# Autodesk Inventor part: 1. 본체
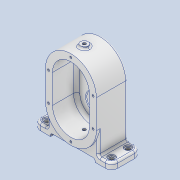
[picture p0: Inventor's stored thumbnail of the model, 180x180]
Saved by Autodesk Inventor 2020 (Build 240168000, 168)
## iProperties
Created: 2021-05
Part Number: 1. 본체
Material: 알루미늄 6061
Document SubType Name: Modeling
Designer: Owner
Density: 2.7 g/cm^3
Appearance: 알루미늄 - 평지
Author: Owner
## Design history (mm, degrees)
sketch "스케치4"
  geometry: L1 (0, -22.5)-(0, 22.5); L2 (40, -22.5)-(40, 22.5); L3 (-40, 22.5)-(-40, -22.5); A1 r 40 centre (0, -22.5) between (-40, -22.5) and (40, -22.5); A2 r 40 centre (0, 22.5) between (40, 22.5) and (-40, 22.5); 2 further points
  constraints: 8 end point, 4 point on circle, 4 tangent, 2 centre point, 1 coincident, 1 midpoint, 1 parallel, 1 vertical
  dimensions: "d15" = 40 radius of A2; "d16" = 45 distance of L3.start L3.end
extrude "돌출4" new body sketch "스케치4" stored distance "d17" = 49; taper "d18" = 0 deg
feature "쉘1" dims "d19" = 11
node "작업 평면1"
sketch "스케치5"
  geometry: L1 (-61, 24.5)-(61, 24.5); L2 (61, 24.5)-(61, -21.5); L3 (61, -21.5)-(-61, -21.5); L4 (-61, -21.5)-(-61, 24.5); L5 (0, 60.783)-(0, -54.984); L6 (90.887, 0)-(-105.505, 0); 1 further point
  constraints: 12 end point, 2 horizontal, 2 parallel, 2 point on line, 1 perpendicular, 1 vertical
  dimensions: "d29" = 122 distance of L1.start L1.end; "d30" = 46 distance of L1.end L2.end; "d31" = 122 diameter of L4 L5 (= d29); "d32" = 49 diameter of L1 L6
extrude "돌출5" join sketch "스케치5" distance "d23" = 10; taper "d24" = 0 deg
sketch "스케치7"
  geometry: L1 (35, 24.5)-(-35, 24.5); L2 (-35, 24.5)-(-35, -21.5); L3 (-35, -21.5)-(35, -21.5); L4 (35, -21.5)-(35, 24.5); L5 (0, 66.655)-(0, -84.262); L6 (-61, 24.5)-(61, 24.5) reference; 1 further point
  constraints: 10 end point, 2 parallel, 1 collinear, 1 horizontal, 1 perpendicular, 1 point on line, 1 vertical
  dimensions: "d33" = 70 distance of L3.end L2.end; "d34" = 46 distance of L2.end L1.end; "d35" = 70 diameter of L4 L5 (= d33)
extrude "돌출7" cut sketch "스케치7" distance "d36" = 5; taper "d37" = 0 deg
node "작업 평면2"
sketch "스케치8"
  geometry: L1 (-40, -24.5)-(40, -24.5) reference; C1 r 6 at (0, -3.5)
  constraints: 1 centre point
  dimensions: "d140" = 21 distance from line of C1.centre L1; "d141" = 12 diameter of C1
extrude "돌출8" join sketch "스케치8" stored distance "d40" = 5; taper "d41" = 0 deg
sketch "스케치20"
  geometry: 2 further points
hole "구멍5" sketch "스케치20" at (0, 0) diameter "d142" = 4.917; stored, may be unused: countersink angle "d146" = 90 deg, drill point angle "d148" = 118 deg; dims "d143" = 12, "d144" = 12, "d145" = 1, "d147" = 17.1
sketch "스케치9"
  geometry: L1 (0, 22.5)-(0, -22.5); L2 (26, 22.5)-(26, -22.5); L3 (-26, -22.5)-(-26, 22.5); L4 (26, 7.5)-(-26, 7.5); A1 r 26 centre (0, 22.5) between (26, 22.5) and (-26, 22.5); A2 r 26 centre (0, -22.5) between (-26, -22.5) and (26, -22.5); 1 further point
  constraints: 10 end point, 4 point on circle, 4 tangent, 2 centre point, 2 point on line, 1 horizontal, 1 midpoint, 1 parallel, 1 vertical
  dimensions: "d49" = 52 distance between parallel lines of L3 L2; "d50" = 45 distance of L1.start L1.end; "d51" = 30 distance from line of L4 L1.end
extrude "돌출9" join sketch "스케치9" distance "d52" = 8; taper "d53" = 0 deg
sketch "스케치10"
  geometry: L1 (93.828, 22.5)-(-161.431, 22.5); L2 (61, 69.5)-(35, 69.5) reference; L3 (0, 93.764)-(0, -111.085); L4 (26, 7.5)-(26, -22.5) reference; L5 (26, 7.5)-(26, 22.5); L6 (-26, -22.5)-(-26, 7.5) reference; L7 (-26, 7.5)-(-26, 22.5); C1 r 14 at (0, -22.5); C2 r 11 at (0, -22.5); A1 r 26 centre (0, -22.5) between (-26, -22.5) and (26, -22.5) reference; A2 r 26 centre (0, 22.5) between (26, 22.5) and (-26, 22.5); 1 further point
  constraints: 8 end point, 3 centre point, 3 point on line, 2 coincident, 2 point on circle, 2 tangent, 1 collinear, 1 horizontal, 1 perpendicular, 1 vertical
  dimensions: "d54" = 28 diameter of C1; "d55" = 22 diameter of C2; "d63" = 47 distance between parallel lines of L1 L2
extrude "돌출10" cut sketch "스케치10" distance "d56" = 4; taper "d57" = 0 deg
extrude "돌출11" cut sketch "스케치10" distance "d58" = 205.5; taper "d59" = 0 deg
sketch "스케치11"
  geometry: C1 r 14 at (0, 0); C2 r 11 at (0, 0) reference; 1 further point
  constraints: 1 centre point
  dimensions: "d60" = 28 diameter of C1
extrude "돌출12" cut sketch "스케치11" distance "d61" = 8; taper "d62" = 0 deg
sketch "스케치12"
  geometry: L1 (0, 0)-(0, 116.266); L2 (96.451, 22.5)-(-125.299, 22.5); L3 (-35, 69.5)-(-61, 69.5) reference; L4 (26, 7.5)-(26, -22.5) reference; L5 (26, 7.5)-(26, 22.5); L6 (-26, 7.5)-(26, 7.5) reference; L7 (-26, 7.5)-(-26, 22.5); A1 r 26 centre (0, 22.5) between (26, 22.5) and (-26, 22.5)
  constraints: 8 end point, 2 perpendicular, 2 point on circle, 2 point on line, 2 tangent, 1 centre point, 1 horizontal, 1 vertical
  dimensions: "d64" = 47 distance between parallel lines of L2 L3
extrude "돌출13" join sketch "스케치12" distance "d65" = 11; taper "d66" = 0 deg
sketch "스케치13"
  geometry: L1 (35, -92)-(61, -92) reference; L2 (0, -116.743)-(0, 80.334); L3 (-83.569, -45)-(143.447, -45); C1 r 14 at (0, -45); C2 r 11 at (0, -45); 1 further point
  constraints: 4 end point, 3 point on line, 2 centre point, 1 coincident, 1 horizontal, 1 vertical
  dimensions: "d68" = 47 distance between parallel lines of L3 L1; "d69" = 28 diameter of C1; "d70" = 22 diameter of C2
extrude "돌출14" cut sketch "스케치13" distance "d71" = 8; taper "d72" = 0 deg
extrude "돌출15" cut sketch "스케치13" distance "d73" = 12; taper "d74" = 0 deg
sketch "스케치14"
  geometry: L1 (-40, -24.5)-(40, -24.5) reference; 2 further points
  dimensions: "d75" = 21 distance from line of point (0, -3.5) L1
hole "구멍2" sketch "스케치14" at (0, -3.5) diameter "d76" = 4.917; stored, may be unused: countersink angle "d80" = 90 deg, drill point angle "d82" = 118 deg; dims "d77" = 16.25, "d78" = 12, "d79" = 1, "d81" = 16.75
sketch "스케치15"
  geometry: L1 (-40, 22.5)-(-40, 59.5); L2 (40, -22.5)-(40, 22.5) reference; L3 (40, 22.5)-(40, 59.5); L4 (61, 59.5)-(15.199, 59.5) reference; L5 (-15.199, 59.5)-(-61, 59.5) reference; A1 r 40 centre (0, 22.5) between (-15.199, 59.5) and (-40, 22.5) reference; A2 r 40 centre (0, 22.5) between (40, 22.5) and (15.199, 59.5) reference; 1 further point
  constraints: 4 end point, 2 vertical, 1 tangent
extrude "돌출16" join sketch "스케치15" distance "d83" = 46; taper "d84" = 0 deg
sketch "스케치16"
  geometry: L1 (34.832, 22.5)-(-35.168, 22.5); L2 (0, 110.946)-(0, -79.008); A1 r 35 centre (-0.168, 22.5) between (34.832, 22.5) and (-35.168, 22.5); 3 further points
  constraints: 4 end point, 3 point on circle, 2 point on line, 1 centre point, 1 coincident, 1 horizontal, 1 midpoint, 1 vertical
  dimensions: "d86" = 70 diameter of A1; "d87" = 22.5 vertical distance of point (0, 0) A1.centre; "d88" = 57.4996 distance of point (0, 0) point (0, 57.5)
hole "구멍3" sketch "스케치16" at (-35.168, 22.5), (34.832, 22.5), (0, 57.5) diameter "d89" = 3.242; stored, may be unused: countersink angle "d93" = 90 deg, drill point angle "d95" = 118 deg; dims "d90" = 8, "d91" = 12, "d92" = 1, "d94" = 10
sketch "스케치17"
  geometry: L1 (61, 24.5)-(40, 24.5) reference; L2 (61, -21.5)-(61, 24.5) reference; L3 (40, -21.5)-(61, -21.5) reference; C1 r 5.5 at (51, 14.5); C2 r 3.3 at (51, 14.5); C3 r 5.5 at (51, -11.5); C4 r 3.3 at (51, -11.5); 1 further point
  constraints: 4 centre point, 2 coincident, 1 vertical alignment
  dimensions: "d96" = 11 diameter of C1; "d97" = 6.6 diameter of C2; "d98" = 11 diameter of C3; "d99" = 6.6 diameter of C4; "d101" = 10 distance from line of C1.centre L1; "d102" = 10 distance from line of L2 C1.centre; "d105" = 10 distance from line of C3.centre L3
fillet "모깎기1" dims "d100" = 10
extrude "돌출17" cut sketch "스케치17" distance "d106" = 46; taper "d107" = 0 deg
extrude "돌출18" cut sketch "스케치17" distance "d108" = 2; taper "d109" = 0 deg
sketch "스케치18"
  geometry: L1 (-59.091, -22.5)-(67.493, -22.5); L2 (0, 82.616)-(0, -92.417); L3 (0, -22.5)-(-72.7, 19.474); L4 (0, -22.5)-(60.116, 12.208); A1 r 20 centre (0, -22.5) between (0, -42.5) and (-17.321, -12.5); 2 further points
  constraints: 8 end point, 5 point on line, 3 point on circle, 1 centre point, 1 horizontal, 1 vertical
  dimensions: "d110" = 40 diameter of A1; "d111" = 120 deg angle of L3 L2; "d112" = 120 deg angle of L4 L3
hole "구멍4" sketch "스케치18" at (0, -42.5), (-17.321, -12.5), (17.321, -12.5) diameter "d113" = 3.242; stored, may be unused: countersink angle "d117" = 90 deg, drill point angle "d119" = 118 deg; dims "d114" = 8, "d115" = 12, "d116" = 1, "d118" = 10
sketch "스케치19"
  geometry: L1 (40, 59.5)-(-40, 59.5); L2 (51, 69.5)-(35, 69.5) reference; L3 (-40, 59.5)-(-40, -22.5) reference; L4 (40, -22.5)-(40, 59.5) reference; 1 further point
  constraints: 2 end point, 2 horizontal, 2 point on line
  dimensions: "d120" = 10 distance between parallel lines of L1 L2
extrude "돌출19" join sketch "스케치19" distance "d121" = 0.5; taper "d122" = 0 deg
fillet "모깎기2" dims "d123" = 5
fillet "모깎기3" dims "d124" = 0.3
fillet "모깎기4" dims "d125" = 0.3
chamfer "모따기1" distance "d126" = 1; stored, may be unused: second distance "d127" = 2, angle "d128" = 45 deg
chamfer "모따기2" distance "d129" = 1; stored, may be unused: second distance "d130" = 2, angle "d131" = 45 deg
fillet "모깎기5" dims "d132" = 3
fillet "모깎기7" dims "d134" = 3
fillet "모깎기8" dims "d135" = 3
fillet "모깎기10" dims "d137" = 3
fillet "모깎기11" dims "d138" = 3
fillet "모깎기13" dims "d149" = 3
node "솔리드2"
mirror "미러1"
mirror "미러2"
feature "A9D066F2-1C7D-4E18-AEED-F7BC21143FA4" dims "d142" = 4.917, "d143" = 12, "d144" = 12, "d145" = 1, "d146" = 90 deg, "d147" = 17.1, "d148" = 118 deg
other parameters: "d20" = -69.5, "d38" = 65.5
